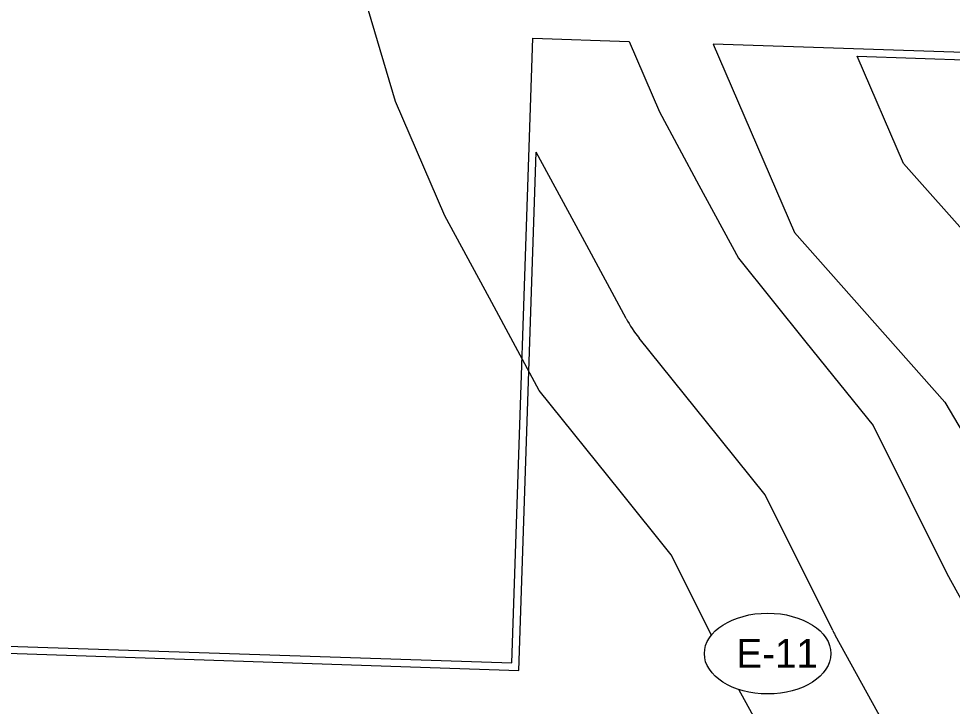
# Model space of a CAD drawing. Extents: x 977239 to 983725, y 1525948 to 1526901.
# Drawn here: x 977835.8 to 978029.8, y 1526609.6 to 1526752.6 of the extents above; entities that cross this region are included whole.
import ezdxf

# ---------------------------------------------------------------- set-up
doc = ezdxf.new("R2010")
doc.units = 0
for name, color, linetype in [('R_Erosion', 7, 'Continuous'), ('R_No Plot', 7, 'Continuous'), ('R_Water', 7, 'Continuous')]:
    doc.layers.add(name, color=color, linetype=linetype)

msp = doc.modelspace()

# ---------------------------------------------------------------- linework, layer by layer
at = {"layer": 'R_Erosion'}
for p, q in [((978010.08, 1526744.75), (978140.02, 1526740.4)), ((977939.78, 1526617.04), (977943.39, 1526724.83)), ((977254.39, 1526640.01), (977939.78, 1526617.04))]:
    msp.add_line(p, q, dxfattribs=at)
for points in [[(978048.06, 1526690.47), (978019.67, 1526722.46), (978010.08, 1526744.75)], [(977962.06, 1526690.21), (977953.87, 1526705.4), (977943.39, 1526724.83)], [(978004.98, 1526625.37), (977990.91, 1526653.57), (977978.74, 1526668.72), (977964.77, 1526686.13)], [(978020.39, 1526566.26), (978025.04, 1526576.78), (978025.06, 1526581.12), (978019.89, 1526598.22), (978005.48, 1526624.4)]]:
    msp.add_lwpolyline(points, dxfattribs=at)
for centre, start, end in [((977985.82, 1526703.03), 208.3403, 218.7588), ((978029.14, 1526637.42), 206.5152, 208.8281)]:
    msp.add_arc(centre, 27, start, end, dxfattribs=at)
msp.add_ellipse((977991.46, 1526620.54), major_axis=(13.15, 0), ratio=0.638788, dxfattribs=at)
at = {"layer": 'R_No Plot'}
for p, q in [((977938.33, 1526618.59), (977942.68, 1526748.51)), ((977942.68, 1526748.51), (977962.65, 1526747.84)), ((978141.57, 1526741.85), (977980.16, 1526747.26)), ((977254.94, 1526641.49), (977938.33, 1526618.59))]:
    msp.add_line(p, q, dxfattribs=at)
for points in [[(977962.65, 1526747.84), (977968.99, 1526733.18), (977977.19, 1526717.98), (977985.41, 1526702.75), (977999.41, 1526685.31), (978013.35, 1526667.94), (978028.7, 1526637.19), (978044.45, 1526608.56), (978051.59, 1526584.97), (978051.51, 1526571.11), (978044.63, 1526555.55), (978037.71, 1526539.89), (978028.88, 1526520.64), (978026.51, 1526506.34)], [(977980.16, 1526747.26), (977997.01, 1526708.07), (978028.27, 1526672.84), (978036.56, 1526658.78), (978044.85, 1526644.73), (978051.19, 1526629.24), (978057.52, 1526613.76), (978061.92, 1526599.69), (978066.35, 1526585.53), (978063.52, 1526567.47), (978046.6, 1526534.53), (978041.96, 1526521.86), (978042.41, 1526506.24)]]:
    msp.add_lwpolyline(points, dxfattribs=at)
msp.add_ellipse((977991.46, 1526620.54), major_axis=(13.15, 0), ratio=0.638788, dxfattribs=at)
at = {"layer": 'R_Water'}
for points in [[(977979.77, 1526624.38), (977971.43, 1526641.1), (977960.81, 1526654.32), (977943.98, 1526675.28), (977933.63, 1526694.48), (977924.41, 1526711.57), (977914.13, 1526735.34), (977902.32, 1526775.14), (977924.5, 1526814.42), (977947.17, 1526829.98), (977971.48, 1526841.44)], [(978000.84, 1526581.76), (977998.58, 1526589.25), (977985.47, 1526613.06)]]:
    msp.add_lwpolyline(points, dxfattribs=at)

# ---------------------------------------------------------------- texts
at = {"layer": 'R_Erosion'}
msp.add_text('E-11', height=5.999, dxfattribs=at).set_placement((977984.96, 1526617.59))

doc.saveas('drawing.dxf')
